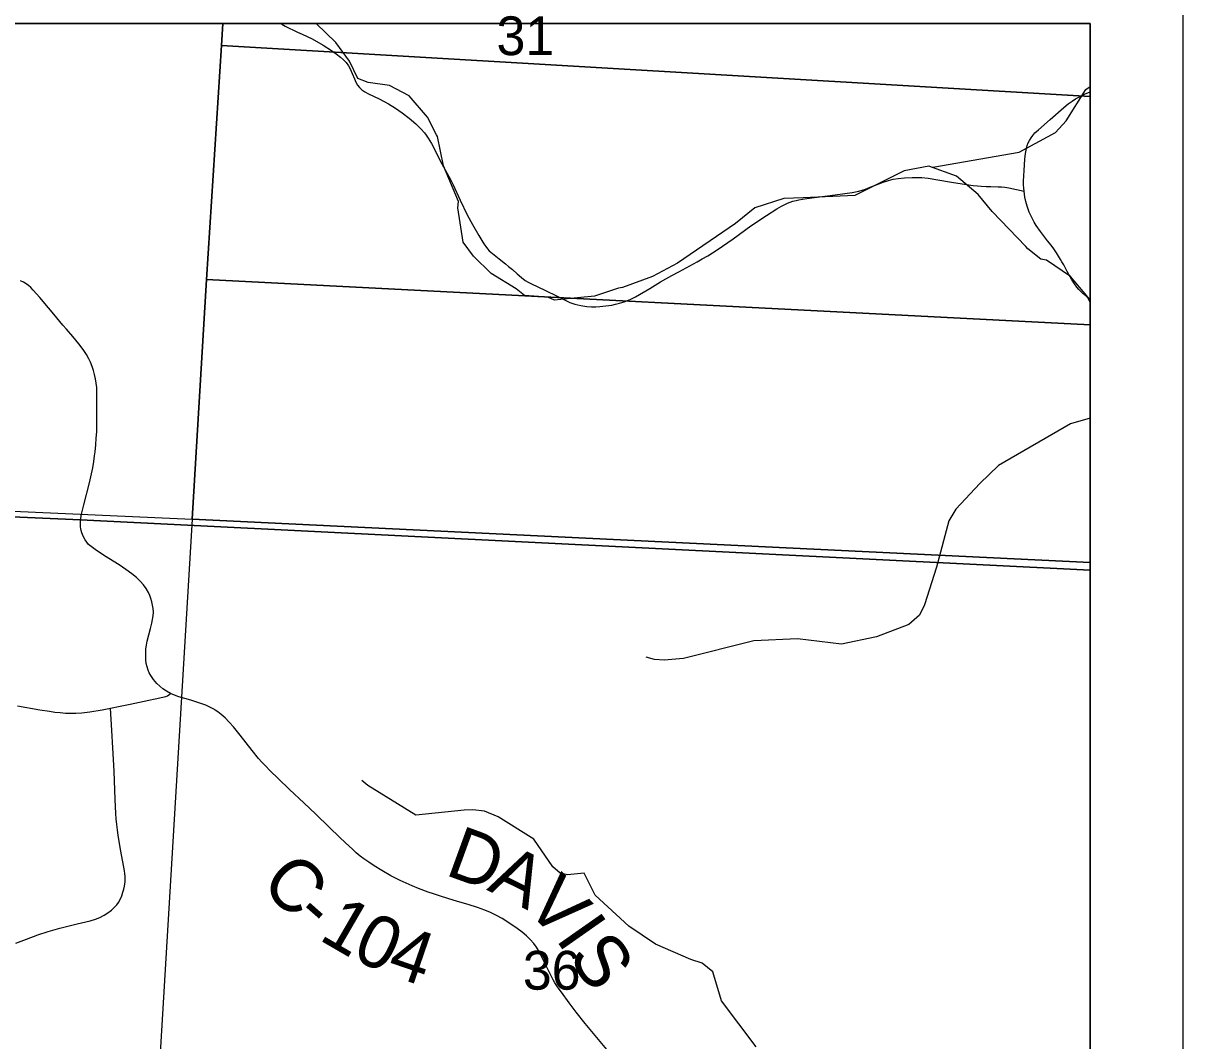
# Model space of a CAD drawing. Extents: x 0 to 34, y 0 to 22.
# Drawn here: x 29.485 to 30.737, y 19.801 to 20.9 of the extents above; entities that cross this region are included whole.
import ezdxf

# ---------------------------------------------------------------- set-up
doc = ezdxf.new("R2010")
doc.units = 0
for name, color, linetype in [('GM_X_County_Road', 7, 'Continuous'), ('GM_X_County_Road_Text', 7, 'Continuous'), ('GM_X_County_Text', 7, 'Continuous'), ('GM_X_Minor_River', 7, 'Continuous'), ('GM_X_Section_Text', 7, 'Continuous'), ('GM_X_State_Shield', 7, 'Continuous'), ('GM_X_Township_Road', 7, 'Continuous'), ('SH_Cut_Line', 7, 'Continuous'), ('SH_Data', 7, 'Continuous')]:
    doc.layers.add(name, color=color, linetype=linetype)

msp = doc.modelspace()

# ---------------------------------------------------------------- linework, layer by layer
at = {"layer": 'GM_X_County_Road'}
for points in [[(30.6297, 20.6082), (30.6271, 20.6105), (30.6249, 20.6127), (30.6228, 20.6154), (30.6201, 20.6189), (30.6171, 20.6238), (30.6142, 20.6291), (30.6125, 20.6324), (30.6086, 20.6394), (30.6067, 20.6426), (30.6051, 20.6451), (30.6008, 20.6524), (30.598, 20.6566), (30.5951, 20.6606), (30.5913, 20.6655), (30.5834, 20.6756), (30.5789, 20.682), (30.5766, 20.6856), (30.5737, 20.6912), (30.5715, 20.6963), (30.5692, 20.7028), (30.5679, 20.7078), (30.5668, 20.7126), (30.5662, 20.7159), (30.5658, 20.7191), (30.5656, 20.7221), (30.5653, 20.7257), (30.5653, 20.7299), (30.5658, 20.7415), (30.5666, 20.7534), (30.5673, 20.7596), (30.5684, 20.765), (30.5693, 20.7682), (30.5703, 20.7711), (30.5717, 20.7739), (30.5734, 20.7767), (30.5753, 20.7793), (30.5776, 20.7819), (30.5813, 20.7854), (30.5939, 20.7964), (30.6087, 20.8095), (30.6136, 20.8133), (30.6177, 20.8162), (30.6215, 20.8187), (30.6257, 20.821), (30.6299, 20.8233), (30.6364, 20.8261), (30.6372, 20.8264)], [(29.5472, 20.3634), (29.5474, 20.3651), (29.5479, 20.3683), (29.5485, 20.3715), (29.5509, 20.3804), (29.557, 20.4039), (29.5603, 20.4202), (29.5616, 20.427), (29.5624, 20.4332), (29.5629, 20.4376), (29.5637, 20.445), (29.5642, 20.4522), (29.5646, 20.4591), (29.5647, 20.466), (29.5649, 20.4797), (29.5649, 20.4946), (29.5648, 20.502), (29.5646, 20.5069), (29.5641, 20.5117), (29.5634, 20.5164), (29.5624, 20.5211), (29.5612, 20.5254), (29.5597, 20.5298), (29.558, 20.5343), (29.5561, 20.5381), (29.5535, 20.5425), (29.5499, 20.5479), (29.5455, 20.554), (29.5388, 20.5621), (29.5319, 20.5701), (29.5282, 20.5744), (29.5183, 20.5862), (29.5127, 20.5929), (29.5033, 20.6042), (29.4962, 20.6122), (29.4935, 20.6148), (29.4909, 20.617), (29.4883, 20.6189), (29.4856, 20.6206), (29.4824, 20.6222)], [(30.6372, 20.6019), (30.6359, 20.603), (30.6303, 20.6076), (30.6297, 20.6082)], [(29.6926, 20.1585), (29.6917, 20.1591), (29.6874, 20.1615), (29.6824, 20.1638), (29.6771, 20.1657), (29.6663, 20.1692), (29.6533, 20.1729), (29.6485, 20.1746), (29.6442, 20.1764), (29.64, 20.1789), (29.6362, 20.1816), (29.6327, 20.1846), (29.6296, 20.1875), (29.6259, 20.1916), (29.6229, 20.1958), (29.6213, 20.1987), (29.6201, 20.2017), (29.619, 20.2052), (29.6182, 20.2089), (29.6177, 20.2128), (29.6175, 20.2168), (29.6175, 20.2207), (29.6178, 20.2248), (29.6183, 20.2289), (29.6191, 20.2331), (29.6209, 20.24), (29.6227, 20.2468), (29.6242, 20.2524), (29.625, 20.2563), (29.6256, 20.2604), (29.6259, 20.2642), (29.6256, 20.2682), (29.625, 20.2721), (29.6242, 20.2756), (29.6232, 20.2791), (29.622, 20.2825), (29.6206, 20.2856), (29.6181, 20.29), (29.615, 20.294), (29.6116, 20.2978), (29.6075, 20.3017), (29.6027, 20.3056), (29.5962, 20.3105), (29.589, 20.3154), (29.5731, 20.3253), (29.563, 20.3319), (29.5588, 20.3351), (29.5559, 20.3376), (29.5538, 20.3401), (29.5521, 20.3425), (29.5503, 20.3457), (29.5492, 20.3481), (29.5485, 20.3502), (29.5478, 20.3524), (29.5474, 20.3545), (29.5471, 20.3564), (29.547, 20.3587), (29.547, 20.3607), (29.5472, 20.3634)], [(30.1154, 19.792), (30.0919, 19.8201), (30.0821, 19.8324), (30.0746, 19.8423), (30.0663, 19.8539), (30.0638, 19.8574), (30.0614, 19.861), (30.0594, 19.8642), (30.0576, 19.8674), (30.053, 19.8761), (30.0456, 19.8911), (30.0425, 19.8972), (30.0393, 19.9026), (30.0364, 19.9067), (30.0327, 19.9109), (30.0286, 19.9148), (30.0239, 19.9188), (30.0184, 19.9229), (30.0117, 19.9275), (30.0022, 19.9334), (29.9962, 19.9368), (29.9896, 19.9401), (29.9838, 19.9425), (29.9798, 19.944), (29.9757, 19.9455), (29.9655, 19.9485), (29.9543, 19.9519), (29.9436, 19.9551), (29.9358, 19.9576), (29.9284, 19.9601), (29.9225, 19.9621), (29.9121, 19.9661), (29.9052, 19.9689), (29.8987, 19.9717), (29.8923, 19.9746), (29.8822, 19.9798), (29.8725, 19.9853), (29.8641, 19.9905), (29.8584, 19.9943), (29.8532, 19.9979), (29.8489, 20.001), (29.8447, 20.0044), (29.841, 20.0079), (29.8329, 20.0155), (29.8271, 20.0211), (29.8156, 20.0323), (29.8013, 20.0462), (29.7882, 20.0586), (29.7729, 20.0729), (29.7604, 20.0849), (29.752, 20.0929), (29.7464, 20.0986), (29.7428, 20.1024), (29.7394, 20.1064), (29.7326, 20.1151), (29.7195, 20.1315), (29.7122, 20.1406), (29.7078, 20.1455), (29.7033, 20.1501), (29.6989, 20.1539), (29.6954, 20.1566), (29.6926, 20.1585)]]:
    msp.add_lwpolyline(points, dxfattribs=at)
at = {"layer": 'GM_X_County_Text'}
msp.add_lwpolyline([(30.6372, 20.3098), (30.6372, 20.9), (28.6466, 20.9), (28.6062, 20.4055), (29.547, 20.3639)], close=True, dxfattribs=at)
msp.add_lwpolyline([(29.4304, 15.2876), (29.5713, 15.2568), (29.7749, 15.1808), (30.0202, 15.1042), (30.4162, 15.0021), (30.5527, 14.9001), (30.6372, 14.8869), (30.6372, 20.3098), (29.547, 20.3639), (28.6062, 20.4055)], dxfattribs=at)
at = {"layer": 'GM_X_Minor_River'}
for points in [[(29.8467, 20.8407), (29.8376, 20.8594), (29.8228, 20.8795), (29.8014, 20.9)], [(29.9326, 20.778), (29.9314, 20.7798), (29.9219, 20.7991), (29.9019, 20.8219), (29.8807, 20.8332), (29.8576, 20.8362), (29.8467, 20.8407)], [(30.4674, 20.745), (30.5606, 20.7611), (30.5998, 20.7823), (30.6111, 20.7948), (30.6325, 20.8287), (30.6372, 20.8319)], [(30.6372, 20.5992), (30.6336, 20.6058), (30.6161, 20.627), (30.59, 20.6444), (30.584, 20.6456), (30.57, 20.6569), (30.5677, 20.6592), (30.5314, 20.6971), (30.5163, 20.7154), (30.4928, 20.7351), (30.4629, 20.746), (30.4365, 20.741), (30.3832, 20.7143), (30.3272, 20.7119), (30.3065, 20.7111), (30.2751, 20.7011), (30.2543, 20.684), (30.1916, 20.6412), (30.1648, 20.6267), (30.1323, 20.6149), (30.1278, 20.6141), (30.1021, 20.6057), (30.0726, 20.6026), (30.059, 20.6014), (30.0518, 20.6044), (30.0265, 20.6063), (30.0174, 20.6135), (29.9905, 20.6301), (29.9716, 20.6487), (29.9602, 20.6639), (29.9545, 20.7011), (29.9553, 20.708), (29.939, 20.7463), (29.9326, 20.778)], [(30.6372, 20.474), (30.6158, 20.4677), (30.5383, 20.4226), (30.5181, 20.4033), (30.4922, 20.3757), (30.4845, 20.3629), (30.4713, 20.3128), (30.4582, 20.2722), (30.4529, 20.2612), (30.4414, 20.251), (30.4065, 20.2379), (30.3689, 20.2298), (30.3212, 20.2354), (30.2742, 20.2334), (30.1983, 20.2142), (30.1774, 20.2124), (30.1668, 20.2132), (30.1577, 20.2159)], [(30.2766, 19.795), (30.2391, 19.8445), (30.2299, 19.8759), (30.2184, 19.8854), (30.2061, 19.8892), (30.168, 19.906), (30.1391, 19.9251), (30.1027, 19.9589), (30.091, 19.9825), (30.0728, 19.9808), (30.0649, 19.9825), (30.0572, 19.9892), (30.0365, 20.0191), (29.9979, 20.0432), (29.9834, 20.0493), (29.9706, 20.0509), (29.9615, 20.0504), (29.9092, 20.0452), (29.8572, 20.0773), (29.851, 20.0824)]]:
    msp.add_lwpolyline(points, dxfattribs=at)
at = {"layer": 'GM_X_State_Shield'}
for points in [[(29.7008, 20.9), (28.6454, 20.9), (28.6121, 20.4119), (29.6678, 20.3647), (29.6833, 20.6236), (29.6992, 20.8762)], [(30.6372, 20.8214), (30.6372, 20.9), (29.7008, 20.9), (29.6992, 20.8762)], [(30.6372, 20.5748), (30.6372, 20.8214), (29.6992, 20.8762), (29.6833, 20.6236)], [(30.6372, 20.318), (30.6372, 20.5748), (29.6833, 20.6236), (29.6678, 20.3647)], [(30.6372, 19.3091), (30.6372, 20.318), (29.6678, 20.3647), (29.6072, 19.3563)]]:
    msp.add_lwpolyline(points, close=True, dxfattribs=at)
at = {"layer": 'GM_X_Township_Road'}
for points in [[(29.7637, 20.9), (29.7644, 20.8995), (29.7682, 20.8973), (29.7725, 20.8949), (29.7771, 20.8927), (29.7815, 20.8907), (29.7865, 20.8884), (29.7971, 20.8834), (29.8091, 20.8766), (29.8182, 20.871), (29.8232, 20.8673), (29.8279, 20.8637), (29.8309, 20.861), (29.8338, 20.8578), (29.8364, 20.8542), (29.8381, 20.851), (29.8403, 20.8461), (29.8429, 20.8403), (29.8444, 20.8367), (29.8463, 20.8335), (29.8483, 20.831), (29.8508, 20.8286), (29.8542, 20.8264), (29.8581, 20.8242), (29.8696, 20.8187), (29.8796, 20.8132), (29.8873, 20.8085), (29.8943, 20.8037), (29.902, 20.7978), (29.9091, 20.7918), (29.9144, 20.7865), (29.9185, 20.7819), (29.9204, 20.7794), (29.9225, 20.7763), (29.926, 20.7705), (29.9296, 20.7636), (29.9356, 20.7516), (29.9429, 20.7382), (29.9461, 20.7323), (29.9495, 20.7257), (29.9569, 20.7094), (29.9647, 20.6935), (29.9703, 20.6831), (29.9772, 20.6713), (29.9826, 20.6622), (29.9846, 20.6593), (29.9864, 20.6568), (29.9885, 20.6546), (29.9919, 20.6516), (29.9992, 20.6459), (30.006, 20.6404), (30.0093, 20.6378), (30.0136, 20.6343), (30.0185, 20.6299), (30.0232, 20.6258), (30.0273, 20.6227), (30.0303, 20.6208), (30.034, 20.6188), (30.0483, 20.6122), (30.0619, 20.6055), (30.0705, 20.6012), (30.0756, 20.5989), (30.0807, 20.597), (30.0839, 20.5961), (30.0874, 20.5954), (30.0938, 20.5945), (30.0989, 20.5942), (30.1034, 20.5942), (30.1079, 20.5943), (30.1144, 20.595), (30.1207, 20.596), (30.1248, 20.5968), (30.1291, 20.5979), (30.1342, 20.5995), (30.1407, 20.6021), (30.1465, 20.6049), (30.1618, 20.6138), (30.1733, 20.621), (30.1792, 20.6244), (30.1855, 20.628), (30.1932, 20.6318), (30.213, 20.6426), (30.2184, 20.6458), (30.2243, 20.6493), (30.2344, 20.6558), (30.2516, 20.6677), (30.2708, 20.6814), (30.2876, 20.6927), (30.2989, 20.6999), (30.3038, 20.7028), (30.3075, 20.7046), (30.3105, 20.706), (30.3134, 20.7071), (30.3163, 20.7081), (30.3196, 20.7089), (30.3227, 20.7097), (30.3267, 20.7104), (30.3312, 20.7111), (30.3397, 20.7123), (30.3619, 20.7149), (30.3723, 20.7164), (30.3803, 20.7176), (30.384, 20.7184), (30.3873, 20.7191), (30.391, 20.7201), (30.3946, 20.7213), (30.3998, 20.7232), (30.4137, 20.7287), (30.4196, 20.7307), (30.4245, 20.7319), (30.43, 20.7328), (30.4369, 20.7334), (30.445, 20.7338), (30.4493, 20.7338), (30.4556, 20.7336), (30.4624, 20.7329), (30.4729, 20.7314), (30.4876, 20.7288), (30.5035, 20.7261), (30.5108, 20.7251), (30.5157, 20.7246), (30.5194, 20.7243), (30.525, 20.724), (30.53, 20.7239), (30.538, 20.7238), (30.5416, 20.7236), (30.545, 20.7233), (30.5492, 20.7226), (30.5577, 20.7208), (30.5658, 20.7191)], [(29.4773, 19.9069), (29.4889, 19.9114), (29.5012, 19.9158), (29.5124, 19.9194), (29.525, 19.923), (29.5437, 19.9277), (29.5576, 19.9311), (29.5635, 19.9329), (29.5681, 19.9348), (29.5726, 19.937), (29.5768, 19.9396), (29.5807, 19.9427), (29.5836, 19.9454), (29.5863, 19.9484), (29.588, 19.9509), (29.5899, 19.9541), (29.5916, 19.958), (29.593, 19.9619), (29.5939, 19.9653), (29.5945, 19.9683), (29.5949, 19.971), (29.5952, 19.9735), (29.5953, 19.9762), (29.5953, 19.9788), (29.5951, 19.9821), (29.5946, 19.985), (29.5907, 20.0062), (29.5877, 20.023), (29.5869, 20.0293), (29.5862, 20.0351), (29.5858, 20.041), (29.5854, 20.0468), (29.5847, 20.062), (29.5834, 20.0928), (29.5821, 20.1178), (29.5811, 20.1364), (29.5794, 20.1606), (29.5898, 20.1627), (29.6006, 20.1651), (29.6157, 20.1684), (29.6327, 20.172), (29.6373, 20.173), (29.6391, 20.1734), (29.6409, 20.1741), (29.6425, 20.175), (29.6442, 20.1764)], [(29.4792, 20.1631), (29.5031, 20.1589), (29.5135, 20.1573), (29.5194, 20.1565), (29.5251, 20.1559), (29.5308, 20.1554), (29.536, 20.1552), (29.5421, 20.1552), (29.5487, 20.1557), (29.5571, 20.1568), (29.5705, 20.1589), (29.5794, 20.1606)]]:
    msp.add_lwpolyline(points, dxfattribs=at)
at = {"layer": 'SH_Cut_Line'}
msp.add_lwpolyline([(29.4304, 15.2876), (29.5713, 15.2568), (29.7749, 15.1808), (30.0202, 15.1042), (30.4162, 15.0021), (30.5527, 14.9001), (30.6372, 14.8869), (30.6372, 20.9), (23.8372, 20.9)], dxfattribs=at)
at = {"layer": 'SH_Data'}
for points in [[(23.7372, 21), (30.7372, 21), (30.7372, 14), (23.7372, 14)], [(23.8372, 20.9), (30.6372, 20.9), (30.6372, 14.1), (23.8372, 14.1)]]:
    msp.add_lwpolyline(points, close=True, dxfattribs=at)

# ---------------------------------------------------------------- texts
at = {"layer": 'GM_X_County_Road_Text'}
for s, rotation, p in [('D', 340.0016, (29.9394, 19.9811)), ('A', 333.7917, (29.9849, 19.9646)), ('C', 315.2926, (29.7399, 19.9692)), ('V', 314.687, (30.0257, 19.9454)), ('-', 318.6757, (29.7757, 19.9339)), ('1', 329.9072, (29.8031, 19.9114)), ('0', 334.9905, (29.8383, 19.8913)), ('I', 305.0173, (30.0592, 19.9118)), ('4', 341.0668, (29.8761, 19.874)), ('S', 304.5862, (30.0725, 19.8928))]:
    msp.add_text(s, height=0.0568, rotation=rotation, dxfattribs=at).set_placement(p)
at = {"layer": 'GM_X_Section_Text'}
for s, p in [('31', (29.9963, 20.8659)), ('36', (30.0247, 19.8567))]:
    msp.add_text(s, height=0.04186, rotation=0, dxfattribs=at).set_placement(p)

doc.saveas('drawing.dxf')
